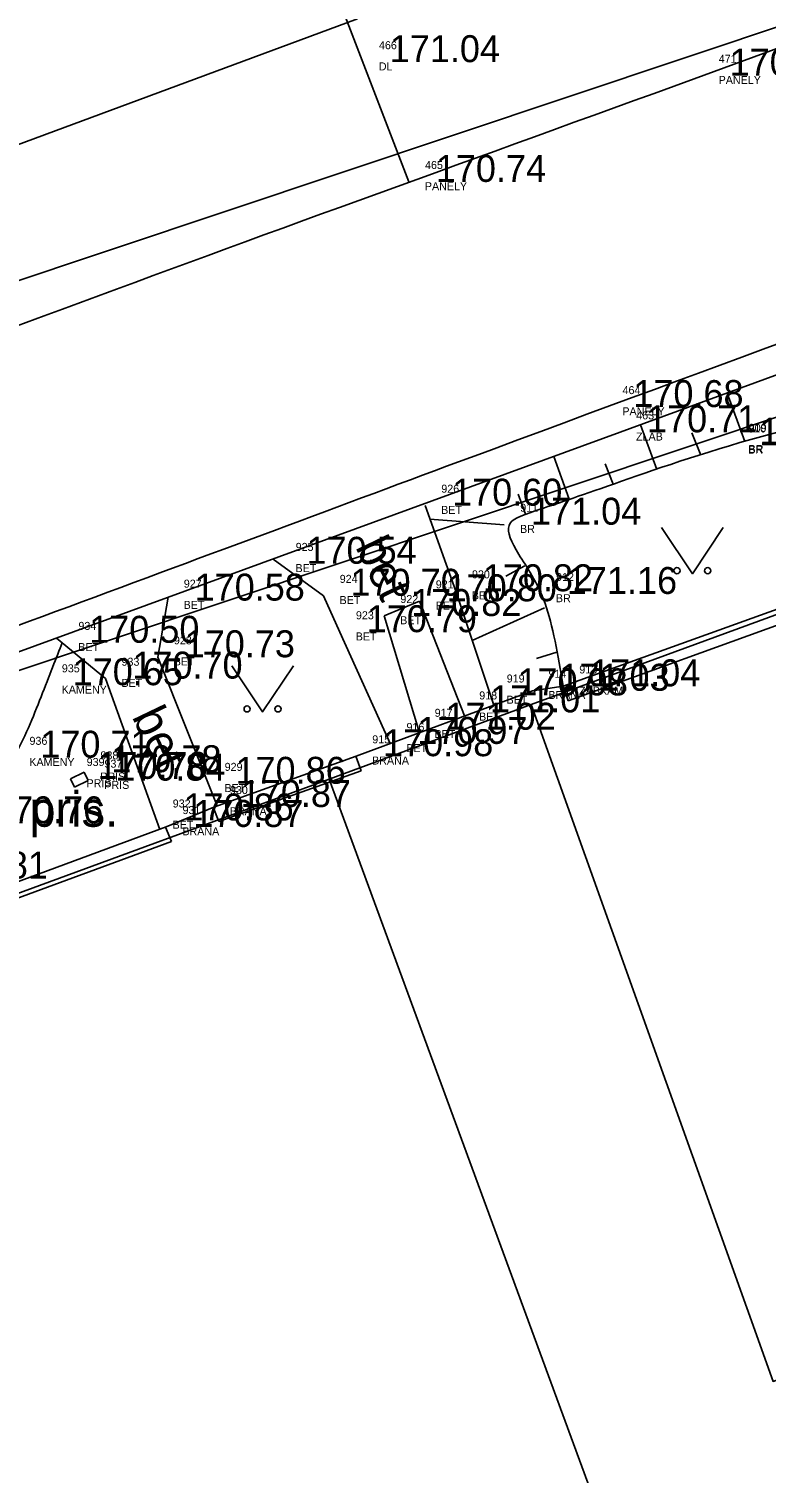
# Model space of a CAD drawing. Extents: x -566117 to -565580, y -1202428 to -1201938.
# Drawn here: x -565883.9 to -565871.93, y -1202054.29 to -1202030.84 of the extents above; entities that cross this region are included whole.
import ezdxf

# ---------------------------------------------------------------- set-up
doc = ezdxf.new("R2010")
doc.units = 0
for name, color, linetype in [('Bod', 7, 'Continuous'), ('Implicitní', 7, 'Continuous'), ('Katastr', 7, 'Continuous'), ('Kod', 7, 'Continuous'), ('Oplocení', 7, 'Continuous'), ('POMOC_POPIS', 7, 'Continuous'), ('Výška', 7, 'Continuous'), ('VÝŠKOPIS (Construction)', 7, 'Continuous'), ('ZN_KULTUR', 7, 'Continuous'), ('Zpevněné plohy', 7, 'Continuous'), ('Číslo', 7, 'Continuous')]:
    doc.layers.add(name, color=color, linetype=linetype)

# ---------------------------------------------------------------- blocks, each defined once
blk = doc.blocks.new('A$C69D74C1E')
at = {"layer": 'Katastr'}
for p, q in [((175.76, 31.81), (246.67, 55.53)), ((251.13, 50.7), (149.9, 16.82)), ((186.36, 37.77), (175.11, 33.59)), ((202.3, 31.45), (189.18, 26.63)), ((185.9, 25.42), (189.18, 26.63)), ((185.9, 25.42), (175.94, 21.76)), ((185.9, 25.42), (193.83, 3.85))]:
    blk.add_line(p, q, dxfattribs=at)
blk.add_lwpolyline([(189.18, 26.63), (193.11, 15.64), (199.49, 18.05), (198.98, 19.41), (202.71, 20.81), (203.22, 19.46), (206.27, 20.67)], dxfattribs=at)
blk = doc.blocks.new('POINT_DISPLAY')
at = {"layer": 'Implicitní'}
blk.add_line((0, 0), (0, 0), dxfattribs=at)
blk = doc.blocks.new('3.140_2')
at = {"layer": 'ZN_KULTUR'}
blk.add_lwpolyline([(-1, 1.5), (0, 0), (1, 1.5)], dxfattribs=at)
for centre in [(-0.5, 0.1), (0.5, 0.1)]:
    blk.add_circle(centre, 0.1, dxfattribs=at)

msp = doc.modelspace()

# ---------------------------------------------------------------- linework, layer by layer
at = {"layer": 'Implicitní'}
for p, q in [((-565878.135, -1202040.37), (-565877.559, -1202040.131)), ((-565883.226, -1202043.015), (-565883.002, -1202042.907)), ((-565883.226, -1202043.015), (-565883.161, -1202043.151)), ((-565883.002, -1202042.907), (-565882.937, -1202043.043)), ((-565883.161, -1202043.151), (-565882.937, -1202043.043))]:
    msp.add_line(p, q, dxfattribs=at)
at = {"layer": 'Oplocení'}
for p, q in [((-565863.826, -1202037.646), (-565875.145, -1202041.747)), ((-565875.229, -1202041.512), (-565869.156, -1202039.325)), ((-565878.59, -1202042.647), (-565875.728, -1202041.584)), ((-565880.9, -1202043.472), (-565878.59, -1202042.647)), ((-565878.506, -1202042.883), (-565878.593, -1202042.648)), ((-565880.816, -1202043.707), (-565878.506, -1202042.883)), ((-565880.9, -1202043.472), (-565881.671, -1202043.796)), ((-565880.816, -1202043.707), (-565880.913, -1202043.477)), ((-565881.586, -1202044.032), (-565881.683, -1202043.802)), ((-565881.586, -1202044.032), (-565889.063, -1202046.782))]:
    msp.add_line(p, q, dxfattribs=at)
at = {"layer": 'VÝŠKOPIS (Construction)'}
for p, q in [((-565872.278, -1202037.539), (-565872.568, -1202036.749)), ((-565873.71, -1202037.99), (-565873.976, -1202037.266)), ((-565872.996, -1202037.757), (-565873.138, -1202037.393)), ((-565875.129, -1202038.475), (-565875.382, -1202037.781)), ((-565874.419, -1202038.231), (-565874.547, -1202037.9)), ((-565875.839, -1202038.716), (-565875.961, -1202038.394)), ((-565876.188, -1202038.887), (-565877.392, -1202038.795)), ((-565875.853, -1202039.558), (-565876.157, -1202039.722)), ((-565875.532, -1202040.236), (-565876.704, -1202040.77)), ((-565875.331, -1202040.958), (-565875.66, -1202041.062))]:
    msp.add_line(p, q, dxfattribs=at)
at = {"layer": 'Zpevněné plohy'}
for p, q in [((-565877.733, -1202033.321), (-565878.79, -1202030.574)), ((-565874.305, -1202037.387), (-565865.482, -1202034.146)), ((-565887.038, -1202042.038), (-565874.305, -1202037.387)), ((-565876.971, -1202039.968), (-565877.47, -1202038.578)), ((-565879.939, -1202039.445), (-565879.118, -1202040.041)), ((-565876.355, -1202041.817), (-565876.971, -1202039.968)), ((-565881.811, -1202041.04), (-565881.64, -1202040.067)), ((-565879.118, -1202040.041), (-565878.855, -1202040.633)), ((-565877.559, -1202040.131), (-565876.83, -1202041.993)), ((-565877.563, -1202042.266), (-565878.135, -1202040.37)), ((-565878.855, -1202040.633), (-565878.037, -1202042.442)), ((-565882.66, -1202041.387), (-565883.452, -1202040.729)), ((-565881.811, -1202041.04), (-565880.843, -1202043.452)), ((-565882.66, -1202041.387), (-565881.778, -1202043.836)), ((-565875.728, -1202041.584), (-565875.229, -1202041.512)), ((-565875.145, -1202041.747), (-565875.229, -1202041.512)), ((-565889.147, -1202046.546), (-565881.671, -1202043.796))]:
    msp.add_line(p, q, dxfattribs=at)
for points in [[(-566046.233, -1202095.491), (-566045.931, -1202095.393), (-566043.978, -1202094.752), (-566040.389, -1202093.195), (-566035.531, -1202091.756), (-566028.975, -1202089.449), (-566022.404, -1202086.74), (-566013.877, -1202083.764), (-566006.988, -1202080.967), (-565999.231, -1202078.336), (-565993.39, -1202076.098), (-565982.391, -1202071.759), (-565967.94, -1202066.641), (-565949.498, -1202059.811), (-565935.388, -1202054.572), (-565926.049, -1202051.077), (-565917.958, -1202048.181), (-565909.827, -1202045.163), (-565898.95, -1202041.321), (-565888.732, -1202037.388), (-565879.759, -1202034.036), (-565869.081, -1202030.224), (-565859.242, -1202026.317), (-565849.297, -1202023.069), (-565843.932, -1202020.848), (-565836.631, -1202018.501), (-565830.04, -1202016.01), (-565822.89, -1202013.251), (-565816.476, -1202011.009), (-565808.989, -1202007.913), (-565802.143, -1202004.887), (-565798.059, -1202002.759), (-565793.947, -1202000.116), (-565789.34, -1201997.072), (-565785.134, -1201994.185), (-565781.539, -1201991.969), (-565778.045, -1201989.73), (-565773.319, -1201986.775), (-565768.281, -1201983.714), (-565761.544, -1201979.725), (-565754.374, -1201977.005), (-565748.201, -1201974.518), (-565743.713, -1201972.786), (-565741.115, -1201971.759), (-565739.444, -1201971.098)], [(-565976.764, -1202074.599), (-565975.068, -1202073.996), (-565970.908, -1202072.515), (-565960.65, -1202068.538), (-565946.466, -1202063.528), (-565932.832, -1202058.326), (-565923.028, -1202054.759), (-565915.71, -1202052.273), (-565903.782, -1202047.572), (-565889.735, -1202042.655), (-565875.782, -1202037.425), (-565865.226, -1202033.562), (-565857.124, -1202030.559), (-565849.222, -1202027.615), (-565843.807, -1202025.74), (-565838.67, -1202023.909), (-565834.175, -1202022.242), (-565830.509, -1202020.913), (-565828.358, -1202020.134)], [(-565875.229, -1202041.512), (-565875.317, -1202040.989), (-565875.473, -1202040.058), (-565876.002, -1202039.33), (-565876.214, -1202038.844), (-565875.786, -1202038.698), (-565874.734, -1202038.344), (-565872.321, -1202037.487), (-565869.088, -1202036.737), (-565866.489, -1202035.505), (-565864.864, -1202034.967), (-565864.43, -1202034.823)], [(-565885.82, -1202044.634), (-565885.512, -1202044.344), (-565884.885, -1202043.754), (-565884.108, -1202042.705), (-565883.696, -1202041.664), (-565883.45, -1202041.035), (-565883.36, -1202040.805)]]:
    msp.add_open_spline(points, degree=3, dxfattribs=at)

# ---------------------------------------------------------------- block references
at = {"layer": 'Bod'}
for p in [(-565878.482, -1202031.376), (-565872.965, -1202031.596), (-565877.733, -1202033.321), (-565874.528, -1202036.977), (-565874.305, -1202037.387), (-565872.486, -1202037.6), (-565872.479, -1202037.589), (-565877.47, -1202038.578), (-565876.188, -1202038.887), (-565879.833, -1202039.522), (-565876.971, -1202039.968), (-565881.65, -1202040.12), (-565879.118, -1202040.041), (-565877.559, -1202040.131), (-565875.606, -1202040.012), (-565878.135, -1202040.37), (-565878.855, -1202040.633), (-565883.36, -1202040.805), (-565881.811, -1202041.04), (-565883.63, -1202041.494), (-565882.66, -1202041.387), (-565875.728, -1202041.584), (-565875.229, -1202041.512), (-565876.407, -1202041.66), (-565876.853, -1202041.935), (-565877.578, -1202042.217), (-565878.034, -1202042.447), (-565878.59, -1202042.647), (-565883.226, -1202043.015), (-565883.002, -1202042.907), (-565882.938, -1202043.044), (-565880.986, -1202043.095), (-565880.9, -1202043.472), (-565881.829, -1202043.69), (-565881.671, -1202043.796)]:
    msp.add_blockref('POINT_DISPLAY', p, dxfattribs=at)
at = {"layer": 'Implicitní'}
msp.add_blockref('A$C69D74C1E', (-566064.93, -1202068.44), dxfattribs=at)
at = {"layer": 'ZN_KULTUR', "xscale": 0.5, "yscale": 0.5}
for p in [(-565873.132, -1202039.685), (-565880.109, -1202041.929)]:
    msp.add_blockref('3.140_2', p, dxfattribs=at)

# ---------------------------------------------------------------- texts
at = {"layer": 'Kod'}
for s, p in [('DL', (-565878.222, -1202031.51)), ('PANELY', (-565872.705, -1202031.73)), ('PANELY', (-565877.474, -1202033.455)), ('PANELY', (-565874.268, -1202037.111)), ('ZLAB', (-565874.046, -1202037.521)), ('BR', (-565872.226, -1202037.734)), ('BR', (-565872.219, -1202037.723)), ('BET', (-565877.21, -1202038.712)), ('BR', (-565875.929, -1202039.021)), ('BET', (-565879.574, -1202039.657)), ('BET', (-565876.712, -1202040.102)), ('BET', (-565881.39, -1202040.254)), ('BET', (-565878.859, -1202040.176)), ('BET', (-565877.299, -1202040.266)), ('BR', (-565875.347, -1202040.146)), ('BET', (-565877.875, -1202040.504)), ('BET', (-565878.596, -1202040.767)), ('BET', (-565883.101, -1202040.94)), ('BET', (-565881.551, -1202041.174)), ('KAMENY', (-565883.37, -1202041.629)), ('BET', (-565882.4, -1202041.522)), ('BRANA', (-565875.469, -1202041.718)), ('ZABKAM', (-565874.97, -1202041.647)), ('BET', (-565876.148, -1202041.794)), ('BET', (-565876.594, -1202042.069)), ('BET', (-565877.318, -1202042.351)), ('BET', (-565877.775, -1202042.581)), ('KAMENY', (-565883.895, -1202042.806)), ('BRANA', (-565878.331, -1202042.782)), ('PRIS', (-565882.967, -1202043.15)), ('PRIS', (-565882.743, -1202043.042)), ('PRIS', (-565882.678, -1202043.178)), ('BET', (-565880.727, -1202043.229)), ('BRANA', (-565880.641, -1202043.606)), ('BET', (-565881.57, -1202043.824)), ('BRANA', (-565881.411, -1202043.931))]:
    msp.add_text(s, height=0.13, dxfattribs=at).set_placement(p)
at = {"layer": 'POMOC_POPIS'}
for p in [(-565878.608, -1202039.245), (-565882.237, -1202042.003)]:
    msp.add_text('bet', height=0.55, rotation=295.6453, dxfattribs=at).set_placement(p)
msp.add_text('pris.', height=0.57, dxfattribs=at).set_placement((-565883.893, -1202043.793))
at = {"layer": 'Výška'}
for s, p in [('171.04', (-565878.044, -1202031.376)), ('170.90', (-565872.527, -1202031.596)), ('170.74', (-565877.296, -1202033.321)), ('170.68', (-565874.09, -1202036.977)), ('170.71', (-565873.868, -1202037.387)), ('171.31', (-565872.048, -1202037.6)), ('171.32', (-565872.041, -1202037.589)), ('170.60', (-565877.032, -1202038.578)), ('171.04', (-565875.751, -1202038.887)), ('170.54', (-565879.396, -1202039.522)), ('170.58', (-565881.212, -1202040.12)), ('170.70', (-565878.681, -1202040.041)), ('170.80', (-565877.121, -1202040.131)), ('170.82', (-565876.534, -1202039.968)), ('171.16', (-565875.169, -1202040.012)), ('170.82', (-565877.697, -1202040.37)), ('170.79', (-565878.418, -1202040.633)), ('170.50', (-565882.923, -1202040.805)), ('170.73', (-565881.373, -1202041.04)), ('170.65', (-565883.192, -1202041.494)), ('170.70', (-565882.222, -1202041.387)), ('171.03', (-565875.291, -1202041.584)), ('171.04', (-565874.792, -1202041.512)), ('170.98', (-565875.97, -1202041.66)), ('171.01', (-565876.416, -1202041.935)), ('171.02', (-565877.14, -1202042.217)), ('170.97', (-565877.597, -1202042.447)), ('170.71', (-565883.717, -1202042.671)), ('170.98', (-565878.153, -1202042.647)), ('170.78', (-565882.565, -1202042.907)), ('170.78', (-565882.789, -1202043.015)), ('170.84', (-565882.5, -1202043.044)), ('170.86', (-565880.549, -1202043.095)), ('170.86', (-565881.392, -1202043.69)), ('170.87', (-565880.463, -1202043.472)), ('170.76', (-565884.485, -1202043.737)), ('170.87', (-565881.233, -1202043.796)), ('170.81', (-565885.383, -1202044.634))]:
    msp.add_text(s, height=0.4375, dxfattribs=at).set_placement(p)
at = {"layer": 'Číslo'}
for s, p in [('466', (-565878.219, -1202031.166)), ('471', (-565872.703, -1202031.386)), ('465', (-565877.471, -1202033.111)), ('464', (-565874.265, -1202036.767)), ('463', (-565874.043, -1202037.177)), ('910', (-565872.223, -1202037.39)), ('909', (-565872.217, -1202037.379)), ('926', (-565877.207, -1202038.368)), ('911', (-565875.926, -1202038.677)), ('925', (-565879.571, -1202039.313)), ('924', (-565878.856, -1202039.832)), ('920', (-565876.709, -1202039.759)), ('912', (-565875.344, -1202039.802)), ('927', (-565881.387, -1202039.91)), ('921', (-565877.297, -1202039.922)), ('922', (-565877.872, -1202040.16)), ('923', (-565878.593, -1202040.423)), ('934', (-565883.098, -1202040.596)), ('928', (-565881.548, -1202040.83)), ('933', (-565882.398, -1202041.178)), ('935', (-565883.367, -1202041.285)), ('919', (-565876.145, -1202041.45)), ('914', (-565875.466, -1202041.374)), ('913', (-565874.967, -1202041.303)), ('918', (-565876.591, -1202041.725)), ('917', (-565877.315, -1202042.007)), ('915', (-565878.328, -1202042.438)), ('916', (-565877.772, -1202042.237)), ('936', (-565883.892, -1202042.462)), ('939', (-565882.964, -1202042.806)), ('938', (-565882.74, -1202042.698)), ('937', (-565882.675, -1202042.834)), ('929', (-565880.724, -1202042.885)), ('930', (-565880.638, -1202043.262)), ('932', (-565881.567, -1202043.48)), ('931', (-565881.408, -1202043.587))]:
    msp.add_text(s, height=0.13, dxfattribs=at).set_placement(p)

doc.saveas('drawing.dxf')
